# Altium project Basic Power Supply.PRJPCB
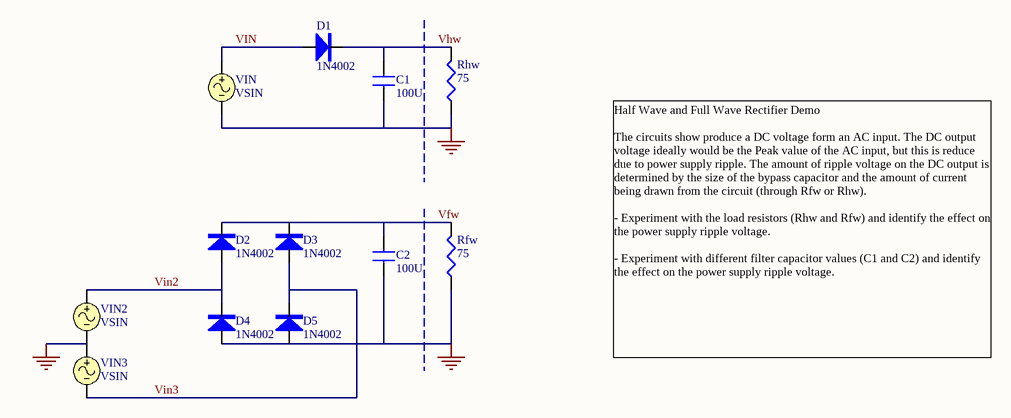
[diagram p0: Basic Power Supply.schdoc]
1 sheet, 12 parts. Net scope: global (net labels, ports and power ports of the same name join across sheets).

## Sheet Basic Power Supply.schdoc: Basic Power Supply
size A4; Organization: Altium Limited; Address1: L3, 12a Rodborough Rd; Address2: Frenchs Forest; Address3: NSW; Address4: Australia 2086; DocumentNumber: 1; SheetNumber: 1; SheetTotal: 1

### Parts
C1  100U
C2  100U
D1  1N4002
D2  1N4002
D3  1N4002
D4  1N4002
D5  1N4002
Rfw  75
Rhw  75
VIN  VSIN
VIN2  VSIN
VIN3  VSIN

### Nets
GND: C1.1 C2.2 D4.1(A) D5.1(A) Rfw.2(BOT) Rhw.2(BOT) VIN.2 VIN2.2 VIN3.1
Vfw: C2.1 D2.2(K) D3.2(K) Rfw.1(TOP)
Vhw: C1.2 D1.2(K) Rhw.1(TOP)
VIN: D1.1(A) VIN.1
Vin2: D2.1(A) D4.2(K) VIN2.1
Vin3: D3.1(A) D5.2(K) VIN3.2

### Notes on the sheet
- Half Wave and Full Wave Rectifier Demo
  The circuits show produce a DC voltage form an AC input. The DC output voltage ideally would be the Peak value of the AC input, but this is reduce due to power supply ripple. The amount of ripple voltage on the DC output is determined by the size of the bypass capacitor and the amount of current being drawn from the circuit (through Rfw or Rhw).
  - Experiment with the load resistors (Rhw and Rfw) and identify the effect on the power supply ripple voltage.
  - Experiment with different filter capacitor values (C1 and C2) and identify the effect on the power supply ripple voltage.

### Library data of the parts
C1 C2 = CAP: Capacitor
D1-D5 = 1N4002: Diode
Rfw Rhw = RES: Resistor; Part Field 1: 0
VIN VIN2 VIN3 = VSIN: Sinusoidal Voltage Source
